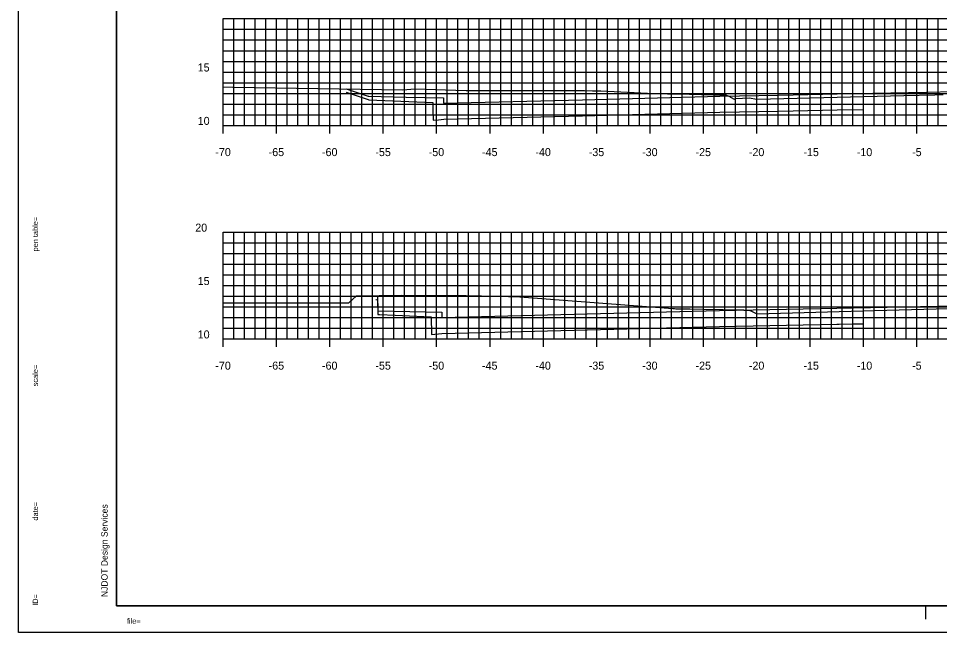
# Model space of a CAD drawing. Extents: x 40011 to 50684, y 49949 to 72236.
# Drawn here: x 40293.9 to 40380.3, y 70934.2 to 70991.7 of the extents above; entities that cross this region are included whole.
import ezdxf

# ---------------------------------------------------------------- set-up
doc = ezdxf.new("R2010")
doc.units = 0
for name, color, linetype in [('1', 7, 'Continuous'), ('41', 7, 'Continuous'), ('51', 7, 'Continuous'), ('52', 7, 'Continuous'), ('53', 7, 'Continuous'), ('54', 7, 'Continuous'), ('55', 7, 'Continuous'), ('57', 7, 'Continuous'), ('58', 7, 'Continuous'), ('59', 7, 'Continuous')]:
    doc.layers.add(name, color=color, linetype=linetype)

msp = doc.modelspace()

# ---------------------------------------------------------------- linework, layer by layer
at = {"layer": '1'}
for p, q in [((40303.141, 71041.691), (40303.141, 70936.691)), ((40303.141, 70936.691), (40468.141, 70936.691)), ((40378.974, 70935.441), (40378.974, 70936.691)), ((40468.641, 70934.191), (40293.946, 70934.191))]:
    msp.add_line(p, q, dxfattribs=at)
at = {"layer": '41'}
for points in [[(40293.946, 71044.191), (40468.641, 71044.191), (40468.641, 70934.191), (40293.946, 70934.191)], [(40303.141, 71041.691), (40468.141, 71041.691), (40468.141, 70936.691), (40303.141, 70936.691)]]:
    msp.add_lwpolyline(points, close=True, dxfattribs=at)
at = {"layer": '51'}
for p, q in [((40313.141, 70981.691), (40313.141, 70991.691)), ((40313.141, 70991.691), (40313.891, 70991.691)), ((40313.141, 70986.691), (40313.891, 70986.691)), ((40313.141, 70981.691), (40313.891, 70981.691)), ((40313.141, 70961.691), (40313.141, 70971.691)), ((40313.141, 70971.691), (40313.891, 70971.691)), ((40313.141, 70966.691), (40313.891, 70966.691)), ((40313.141, 70961.691), (40313.891, 70961.691))]:
    msp.add_line(p, q, dxfattribs=at)
at = {"layer": '52'}
for p, q in [((40313.141, 70981.691), (40453.141, 70981.691)), ((40313.141, 70980.941), (40313.141, 70981.691)), ((40318.141, 70980.941), (40318.141, 70981.691)), ((40323.141, 70980.941), (40323.141, 70981.691)), ((40328.141, 70980.941), (40328.141, 70981.691)), ((40333.141, 70980.941), (40333.141, 70981.691)), ((40338.141, 70980.941), (40338.141, 70981.691)), ((40343.141, 70980.941), (40343.141, 70981.691)), ((40348.141, 70980.941), (40348.141, 70981.691)), ((40353.141, 70980.941), (40353.141, 70981.691)), ((40358.141, 70980.941), (40358.141, 70981.691)), ((40363.141, 70980.941), (40363.141, 70981.691)), ((40368.141, 70980.941), (40368.141, 70981.691)), ((40373.141, 70980.941), (40373.141, 70981.691)), ((40378.141, 70980.941), (40378.141, 70981.691)), ((40313.141, 70961.691), (40453.141, 70961.691)), ((40313.141, 70960.941), (40313.141, 70961.691)), ((40318.141, 70960.941), (40318.141, 70961.691)), ((40323.141, 70960.941), (40323.141, 70961.691)), ((40328.141, 70960.941), (40328.141, 70961.691)), ((40333.141, 70960.941), (40333.141, 70961.691)), ((40338.141, 70960.941), (40338.141, 70961.691)), ((40343.141, 70960.941), (40343.141, 70961.691)), ((40348.141, 70960.941), (40348.141, 70961.691)), ((40353.141, 70960.941), (40353.141, 70961.691)), ((40358.141, 70960.941), (40358.141, 70961.691)), ((40363.141, 70960.941), (40363.141, 70961.691)), ((40368.141, 70960.941), (40368.141, 70961.691)), ((40373.141, 70960.941), (40373.141, 70961.691)), ((40378.141, 70960.941), (40378.141, 70961.691))]:
    msp.add_line(p, q, dxfattribs=at)
at = {"layer": '53'}
for p, q in [((40313.141, 70990.691), (40453.141, 70990.691)), ((40313.141, 70989.691), (40453.141, 70989.691)), ((40313.141, 70988.691), (40453.141, 70988.691)), ((40313.141, 70987.691), (40453.141, 70987.691)), ((40313.141, 70985.691), (40453.141, 70985.691)), ((40313.141, 70984.691), (40453.141, 70984.691)), ((40313.141, 70983.691), (40453.141, 70983.691)), ((40313.141, 70982.691), (40453.141, 70982.691)), ((40313.141, 70970.691), (40453.141, 70970.691)), ((40313.141, 70969.691), (40453.141, 70969.691)), ((40313.141, 70968.691), (40453.141, 70968.691)), ((40313.141, 70967.691), (40453.141, 70967.691)), ((40313.141, 70965.691), (40453.141, 70965.691)), ((40313.141, 70964.691), (40453.141, 70964.691)), ((40313.141, 70963.691), (40453.141, 70963.691)), ((40313.141, 70962.691), (40453.141, 70962.691))]:
    msp.add_line(p, q, dxfattribs=at)
at = {"layer": '54'}
for p, q in [((40314.141, 70981.691), (40314.141, 70991.691)), ((40315.141, 70981.691), (40315.141, 70991.691)), ((40316.141, 70981.691), (40316.141, 70991.691)), ((40317.141, 70981.691), (40317.141, 70991.691)), ((40319.141, 70981.691), (40319.141, 70991.691)), ((40320.141, 70981.691), (40320.141, 70991.691)), ((40321.141, 70981.691), (40321.141, 70991.691)), ((40322.141, 70981.691), (40322.141, 70991.691)), ((40324.141, 70981.691), (40324.141, 70991.691)), ((40325.141, 70981.691), (40325.141, 70991.691)), ((40326.141, 70981.691), (40326.141, 70991.691)), ((40327.141, 70981.691), (40327.141, 70991.691)), ((40329.141, 70981.691), (40329.141, 70991.691)), ((40330.141, 70981.691), (40330.141, 70991.691)), ((40331.141, 70981.691), (40331.141, 70991.691)), ((40332.141, 70981.691), (40332.141, 70991.691)), ((40334.141, 70981.691), (40334.141, 70991.691)), ((40335.141, 70981.691), (40335.141, 70991.691)), ((40336.141, 70981.691), (40336.141, 70991.691)), ((40337.141, 70981.691), (40337.141, 70991.691)), ((40339.141, 70981.691), (40339.141, 70991.691)), ((40340.141, 70981.691), (40340.141, 70991.691)), ((40341.141, 70981.691), (40341.141, 70991.691)), ((40342.141, 70981.691), (40342.141, 70991.691)), ((40344.141, 70981.691), (40344.141, 70991.691)), ((40345.141, 70981.691), (40345.141, 70991.691)), ((40346.141, 70981.691), (40346.141, 70991.691)), ((40347.141, 70981.691), (40347.141, 70991.691)), ((40349.141, 70981.691), (40349.141, 70991.691)), ((40350.141, 70981.691), (40350.141, 70991.691)), ((40351.141, 70981.691), (40351.141, 70991.691)), ((40352.141, 70981.691), (40352.141, 70991.691)), ((40354.141, 70981.691), (40354.141, 70991.691)), ((40355.141, 70981.691), (40355.141, 70991.691)), ((40356.141, 70981.691), (40356.141, 70991.691)), ((40357.141, 70981.691), (40357.141, 70991.691)), ((40359.141, 70981.691), (40359.141, 70991.691)), ((40360.141, 70981.691), (40360.141, 70991.691)), ((40361.141, 70981.691), (40361.141, 70991.691)), ((40362.141, 70981.691), (40362.141, 70991.691)), ((40364.141, 70981.691), (40364.141, 70991.691)), ((40365.141, 70981.691), (40365.141, 70991.691)), ((40366.141, 70981.691), (40366.141, 70991.691)), ((40367.141, 70981.691), (40367.141, 70991.691)), ((40369.141, 70981.691), (40369.141, 70991.691)), ((40370.141, 70981.691), (40370.141, 70991.691)), ((40371.141, 70981.691), (40371.141, 70991.691)), ((40372.141, 70981.691), (40372.141, 70991.691)), ((40374.141, 70981.691), (40374.141, 70991.691)), ((40375.141, 70981.691), (40375.141, 70991.691)), ((40376.141, 70981.691), (40376.141, 70991.691)), ((40377.141, 70981.691), (40377.141, 70991.691)), ((40379.141, 70981.691), (40379.141, 70991.691)), ((40380.141, 70981.691), (40380.141, 70991.691)), ((40314.141, 70961.691), (40314.141, 70971.691)), ((40315.141, 70961.691), (40315.141, 70971.691)), ((40316.141, 70961.691), (40316.141, 70971.691)), ((40317.141, 70961.691), (40317.141, 70971.691)), ((40319.141, 70961.691), (40319.141, 70971.691)), ((40320.141, 70961.691), (40320.141, 70971.691)), ((40321.141, 70961.691), (40321.141, 70971.691)), ((40322.141, 70961.691), (40322.141, 70971.691)), ((40324.141, 70961.691), (40324.141, 70971.691)), ((40325.141, 70961.691), (40325.141, 70971.691)), ((40326.141, 70961.691), (40326.141, 70971.691)), ((40327.141, 70961.691), (40327.141, 70971.691)), ((40329.141, 70961.691), (40329.141, 70971.691)), ((40330.141, 70961.691), (40330.141, 70971.691)), ((40331.141, 70961.691), (40331.141, 70971.691)), ((40332.141, 70961.691), (40332.141, 70971.691)), ((40334.141, 70961.691), (40334.141, 70971.691)), ((40335.141, 70961.691), (40335.141, 70971.691)), ((40336.141, 70961.691), (40336.141, 70971.691)), ((40337.141, 70961.691), (40337.141, 70971.691)), ((40339.141, 70961.691), (40339.141, 70971.691)), ((40340.141, 70961.691), (40340.141, 70971.691)), ((40341.141, 70961.691), (40341.141, 70971.691)), ((40342.141, 70961.691), (40342.141, 70971.691)), ((40344.141, 70961.691), (40344.141, 70971.691)), ((40345.141, 70961.691), (40345.141, 70971.691)), ((40346.141, 70961.691), (40346.141, 70971.691)), ((40347.141, 70961.691), (40347.141, 70971.691)), ((40349.141, 70961.691), (40349.141, 70971.691)), ((40350.141, 70961.691), (40350.141, 70971.691)), ((40351.141, 70961.691), (40351.141, 70971.691)), ((40352.141, 70961.691), (40352.141, 70971.691)), ((40354.141, 70961.691), (40354.141, 70971.691)), ((40355.141, 70961.691), (40355.141, 70971.691)), ((40356.141, 70961.691), (40356.141, 70971.691)), ((40357.141, 70961.691), (40357.141, 70971.691)), ((40359.141, 70961.691), (40359.141, 70971.691)), ((40360.141, 70961.691), (40360.141, 70971.691)), ((40361.141, 70961.691), (40361.141, 70971.691)), ((40362.141, 70961.691), (40362.141, 70971.691)), ((40364.141, 70961.691), (40364.141, 70971.691)), ((40365.141, 70961.691), (40365.141, 70971.691)), ((40366.141, 70961.691), (40366.141, 70971.691)), ((40367.141, 70961.691), (40367.141, 70971.691)), ((40369.141, 70961.691), (40369.141, 70971.691)), ((40370.141, 70961.691), (40370.141, 70971.691)), ((40371.141, 70961.691), (40371.141, 70971.691)), ((40372.141, 70961.691), (40372.141, 70971.691)), ((40374.141, 70961.691), (40374.141, 70971.691)), ((40375.141, 70961.691), (40375.141, 70971.691)), ((40376.141, 70961.691), (40376.141, 70971.691)), ((40377.141, 70961.691), (40377.141, 70971.691)), ((40379.141, 70961.691), (40379.141, 70971.691)), ((40380.141, 70961.691), (40380.141, 70971.691))]:
    msp.add_line(p, q, dxfattribs=at)
at = {"layer": '55'}
for p, q in [((40313.141, 70991.691), (40453.141, 70991.691)), ((40313.141, 70981.691), (40313.141, 70991.691)), ((40318.141, 70981.691), (40318.141, 70991.691)), ((40323.141, 70981.691), (40323.141, 70991.691)), ((40328.141, 70981.691), (40328.141, 70991.691)), ((40333.141, 70981.691), (40333.141, 70991.691)), ((40338.141, 70981.691), (40338.141, 70991.691)), ((40343.141, 70981.691), (40343.141, 70991.691)), ((40348.141, 70981.691), (40348.141, 70991.691)), ((40353.141, 70981.691), (40353.141, 70991.691)), ((40358.141, 70981.691), (40358.141, 70991.691)), ((40363.141, 70981.691), (40363.141, 70991.691)), ((40368.141, 70981.691), (40368.141, 70991.691)), ((40373.141, 70981.691), (40373.141, 70991.691)), ((40378.141, 70981.691), (40378.141, 70991.691)), ((40313.141, 70986.691), (40453.141, 70986.691)), ((40313.141, 70981.691), (40453.141, 70981.691)), ((40313.141, 70971.691), (40453.141, 70971.691)), ((40313.141, 70961.691), (40313.141, 70971.691)), ((40318.141, 70961.691), (40318.141, 70971.691)), ((40323.141, 70961.691), (40323.141, 70971.691)), ((40328.141, 70961.691), (40328.141, 70971.691)), ((40333.141, 70961.691), (40333.141, 70971.691)), ((40338.141, 70961.691), (40338.141, 70971.691)), ((40343.141, 70961.691), (40343.141, 70971.691)), ((40348.141, 70961.691), (40348.141, 70971.691)), ((40353.141, 70961.691), (40353.141, 70971.691)), ((40358.141, 70961.691), (40358.141, 70971.691)), ((40363.141, 70961.691), (40363.141, 70971.691)), ((40368.141, 70961.691), (40368.141, 70971.691)), ((40373.141, 70961.691), (40373.141, 70971.691)), ((40378.141, 70961.691), (40378.141, 70971.691)), ((40313.141, 70966.691), (40453.141, 70966.691)), ((40313.141, 70961.691), (40453.141, 70961.691))]:
    msp.add_line(p, q, dxfattribs=at)
at = {"layer": '57'}
for points in [[(40313.141, 70985.294), (40314.052, 70985.274), (40329.964, 70985.032), (40331.112, 70985.11), (40335.915, 70984.956), (40346.761, 70984.967), (40347.008, 70984.961), (40347.744, 70984.944), (40348.54, 70984.922), (40352.91, 70984.725), (40354.774, 70984.664), (40355.721, 70984.638), (40359.099, 70984.568), (40360.242, 70984.57), (40360.518, 70984.422), (40361.023, 70984.157), (40361.138, 70984.205), (40362.447, 70984.281), (40363.106, 70984.138), (40363.173, 70984.136), (40376.918, 70984.479), (40379.834, 70984.553), (40380.602, 70984.571)], [(40313.141, 70965.086), (40323.75, 70965.071), (40324.378, 70965.071), (40324.907, 70965.059), (40324.925, 70965.07), (40325.639, 70965.731), (40329.842, 70965.779), (40335.899, 70965.752), (40338.782, 70965.705), (40339.178, 70965.698), (40339.589, 70965.689), (40339.879, 70965.681), (40340.522, 70965.656), (40355.289, 70964.541), (40355.337, 70964.539), (40355.442, 70964.534), (40355.57, 70964.527), (40355.683, 70964.521), (40356.072, 70964.508), (40356.865, 70964.498), (40358.125, 70964.478), (40361.896, 70964.405), (40361.915, 70964.398), (40362.424, 70964.367), (40362.463, 70964.383), (40363.138, 70964.058), (40363.192, 70964.044), (40374.161, 70964.343), (40382.274, 70964.571)]]:
    msp.add_lwpolyline(points, dxfattribs=at)
at = {"layer": '58'}
for points in [[(40324.664, 70984.793), (40326.725, 70984.106), (40326.789, 70984.085), (40329.792, 70983.967), (40332.792, 70983.849), (40332.798, 70983.017), (40332.803, 70982.18), (40333.3, 70982.227), (40333.799, 70982.274), (40346.799, 70982.599), (40359.685, 70982.921), (40365.185, 70983.031), (40370.686, 70983.141), (40373.136, 70983.19), (40373.141, 70983.19)], [(40327.448, 70965.39), (40327.558, 70965.358), (40327.602, 70965.423), (40327.631, 70963.991), (40327.785, 70963.984), (40329.263, 70963.921), (40332.635, 70963.775), (40332.645, 70962.106), (40333.641, 70962.2), (40359.641, 70962.85), (40370.641, 70963.07), (40370.867, 70963.075), (40372.132, 70963.1), (40373.084, 70963.119), (40373.141, 70963.12), (40373.141, 70963.12), (40373.141, 70963.12)]]:
    msp.add_lwpolyline(points, dxfattribs=at)
at = {"layer": '59'}
for points in [[(40324.664, 70985.123), (40326.725, 70984.436), (40326.788, 70984.415), (40330.288, 70984.345), (40333.788, 70984.275), (40333.793, 70984.025), (40333.798, 70983.775), (40346.798, 70984.1), (40359.684, 70984.422), (40365.184, 70984.532), (40370.686, 70984.642), (40379.035, 70984.809), (40381.641, 70984.861)], [(40327.602, 70965.753), (40327.631, 70964.321), (40333.631, 70964.201), (40333.641, 70963.701), (40359.641, 70964.351), (40370.641, 70964.571), (40381.632, 70964.791), (40381.778, 70965.288), (40381.793, 70965.288), (40383.639, 70965.257), (40385.481, 70965.226), (40385.486, 70965.226), (40385.632, 70964.724), (40388.641, 70964.679), (40399.641, 70964.459), (40414.298, 70964.092), (40414.308, 70964.592), (40421.308, 70964.732), (40421.311, 70964.732), (40424.292, 70964.79), (40424.295, 70964.63), (40424.302, 70964.29)]]:
    msp.add_lwpolyline(points, dxfattribs=at)

# ---------------------------------------------------------------- texts
at = {"layer": '1'}
for s, height, rotation, p in [('...................pentable..................', 0.0072, 90, (40295.779, 70973.869)), ('pen table=', 0.5, 90, (40295.779, 70969.885)), ('scale=', 0.5, 90, (40295.779, 70957.257)), ('......scale......', 0.0072, 90, (40295.779, 70959.703)), ('date=', 0.5, 90, (40295.779, 70944.681)), ('.......time......', 0.0072, 90, (40295.779, 70946.869)), ('NJDOT Design Services', 0.6, 90, (40302.308, 70937.513)), ('ID=', 0.5, 90, (40295.779, 70936.696)), ('............who............', 0.0072, 90, (40295.779, 70938.024)), ('file=', 0.5, 360, (40304.114, 70935.024)), ('...................bob..................', 0.0072, 360, (40305.779, 70935.024))]:
    msp.add_text(s, height=height, rotation=rotation, dxfattribs=at).set_placement(p)
at = {"layer": '51'}
for s, height, p in [('15', 0.75, (40310.748, 70986.741)), ('10', 0.75, (40310.748, 70981.741)), ('-', 0.0001, (40313.141, 70981.691)), ('20', 0.75, (40310.52, 70971.741)), ('15', 0.75, (40310.748, 70966.741)), ('10', 0.75, (40310.748, 70961.741)), ('-', 0.0001, (40313.141, 70961.691))]:
    msp.add_text(s, height=height, dxfattribs=at).set_placement(p)
at = {"layer": '52'}
for s, p in [('-70', (40312.401, 70978.816)), ('-65', (40317.396, 70978.816)), ('-60', (40322.396, 70978.816)), ('-55', (40327.398, 70978.816)), ('-50', (40332.398, 70978.816)), ('-45', (40337.393, 70978.816)), ('-40', (40342.393, 70978.816)), ('-35', (40347.397, 70978.816)), ('-30', (40352.397, 70978.816)), ('-25', (40357.401, 70978.816)), ('-20', (40362.401, 70978.816)), ('-15', (40367.515, 70978.816)), ('-10', (40372.515, 70978.816)), ('-5', (40377.7, 70978.816)), ('-70', (40312.401, 70958.816)), ('-65', (40317.396, 70958.816)), ('-60', (40322.396, 70958.816)), ('-55', (40327.398, 70958.816)), ('-50', (40332.398, 70958.816)), ('-45', (40337.393, 70958.816)), ('-40', (40342.393, 70958.816)), ('-35', (40347.397, 70958.816)), ('-30', (40352.397, 70958.816)), ('-25', (40357.401, 70958.816)), ('-20', (40362.401, 70958.816)), ('-15', (40367.515, 70958.816)), ('-10', (40372.515, 70958.816)), ('-5', (40377.7, 70958.816))]:
    msp.add_text(s, height=0.75, dxfattribs=at).set_placement(p)

doc.saveas('drawing.dxf')
